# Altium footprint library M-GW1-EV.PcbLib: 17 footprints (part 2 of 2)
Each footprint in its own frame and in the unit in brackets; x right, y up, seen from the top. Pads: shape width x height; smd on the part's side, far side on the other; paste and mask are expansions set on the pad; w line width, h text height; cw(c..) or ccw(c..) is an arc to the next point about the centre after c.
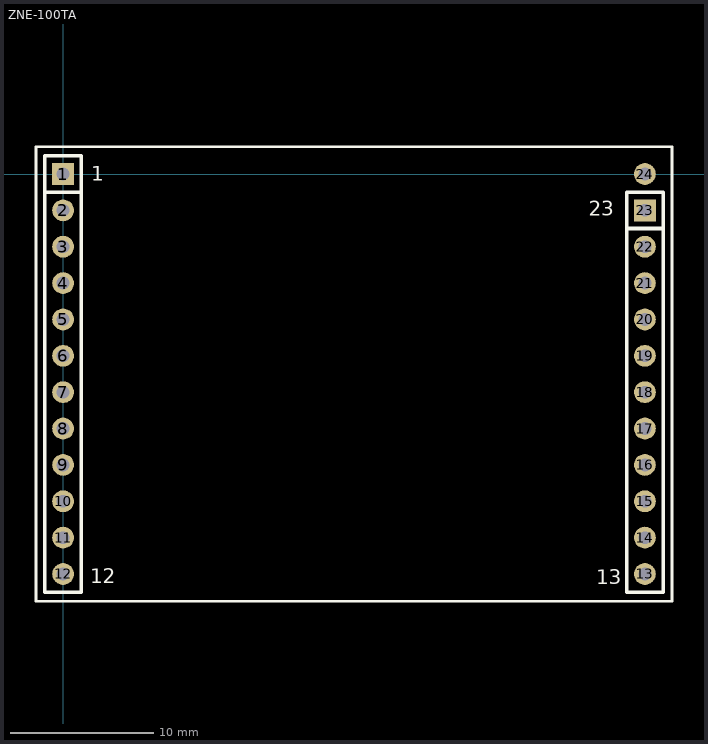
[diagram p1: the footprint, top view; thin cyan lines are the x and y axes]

## ZNE-100TA [mil]
height 133.86
pads (24):
  rect 60x60 hole 35: 1(0,0) 23(1600,-100)
  round 60 hole 35: 2(0,-100) 3(0,-200) 4(0,-300) 5(0,-400) 6(0,-500) 7(0,-600) 8(0,-700) 9(0,-800) 10(0,-900) 11(0,-1000) 12(0,-1100) 13(1600,-1100) 14(1600,-1000) 15(1600,-900) 16(1600,-800) 17(1600,-700) 18(1600,-600) 19(1600,-500) 20(1600,-400) 21(1600,-300) 22(1600,-200) 24(1600,0)
Top Overlay:
  lines w8: -75,-1175 1675,-1175 1675,75 -75,75 -75,-1175
  lines w10: -50,-50 50,-50 ; 1550,-850 1550,-50 ; 1550,-150 1650,-150 ; 1550,-50 1550,-1150 1650,-1150 1650,-50 1550,-50 ; -50,-1150 -50,50 50,50 50,-1150 -50,-1150
  text "13" at 1466,-1128 h40
  text "12" at 74,-1126 h40
  text "23" at 1445,-115 h40
  text "1" at 77,-19 h40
